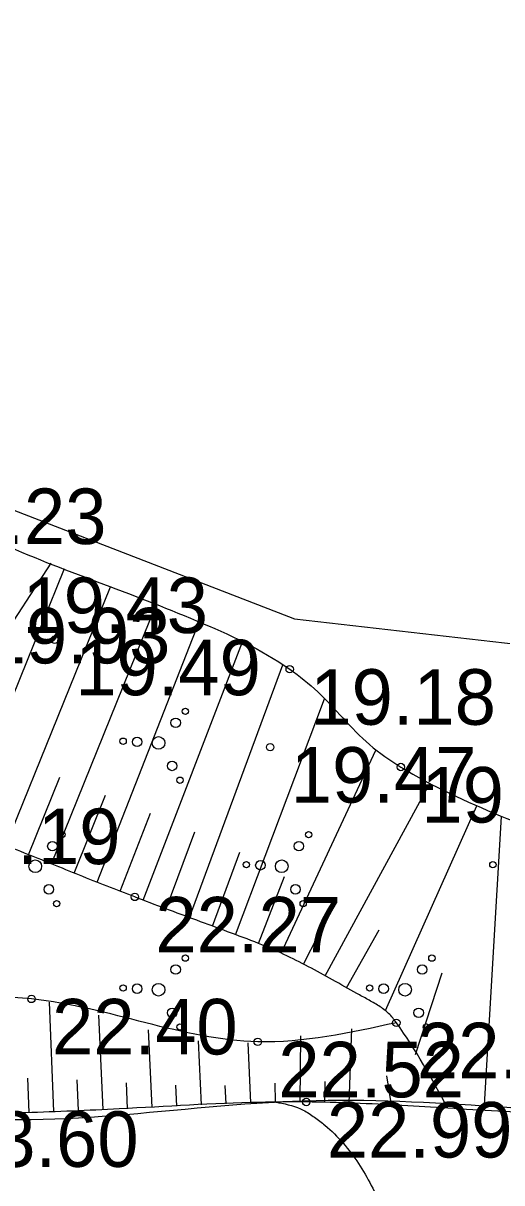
# Model space of a CAD drawing. Extents: x 521824 to 524158, y 294774 to 296228.
# Drawn here: x 522039.75 to 522049.46, y 296028.59 to 296052.08 of the extents above; entities that cross this region are included whole.
import ezdxf

# ---------------------------------------------------------------- set-up
doc = ezdxf.new("R2010")
doc.units = 0
for name, color, linetype in [('HIDG_PLIN_####_####_#', 7, 'Continuous'), ('RAMI_UZMR_####_####_#', 7, 'Continuous'), ('RELJ_AATZ_####_TKST_#', 7, 'Continuous'), ('RELJ_ELEM_####_####_#', 7, 'Continuous'), ('RELJ_HORZ_PAMT_####_#', 7, 'Continuous'), ('RELJ_NOGA_####_####_#', 7, 'Continuous'), ('RELJ_NOGL_####_####_#', 7, 'Continuous'), ('TERT_ELEM_####_####_#', 7, 'Continuous'), ('TERT_KONT_####_####_#', 7, 'Continuous')]:
    doc.layers.add(name, color=color, linetype=linetype)

msp = doc.modelspace()

# ---------------------------------------------------------------- linework, layer by layer
at = {"layer": 'HIDG_PLIN_####_####_#'}
for points in [[(522031.3024014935, 296050.69658941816), (522031.173, 296049.489), (522031.61527393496, 296047.3902310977), (522033.10356148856, 296045.5980747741), (522035.14856829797, 296044.0423810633), (522036.22693693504, 296043.3312858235), (522037.261, 296042.653), (522039.2199077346, 296041.5852114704), (522041.25685016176, 296040.7651794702), (522043.27086750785, 296039.9738077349), (522045.161, 296038.9920000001), (522045.72860179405, 296038.53251211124), (522046.2439666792, 296037.9979730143), (522046.78134822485, 296037.46519741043), (522047.41500000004, 296037.011), (522049.42746192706, 296036.01895480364)], [(522049.42746192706, 296036.01895480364), (522051.6761867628, 296035.315217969), (522053.955, 296035.24), (522056.633707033, 296035.67311548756), (522059.3118930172, 296036.18519992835), (522061.99338249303, 296036.7034344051), (522064.68200000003, 296037.1550000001), (522072.34578787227, 296038.30977781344), (522080.041, 296039.254), (522082.3829693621, 296039.4026833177), (522084.7289845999, 296039.4469387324), (522089.4278641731, 296039.3541311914), (522094.12706165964, 296039.23950805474), (522098.81599999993, 296039.367), (522103.92164475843, 296039.766797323), (522109.0253597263, 296040.2048024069), (522114.1296448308, 296040.6406562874), (522119.237, 296041.034), (522140.36100000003, 296042.353), (522146.41991366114, 296042.5193566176), (522152.48640362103, 296042.45253070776), (522158.5546917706, 296042.40393944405), (522161.5877045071, 296042.4650496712), (522164.619, 296042.625), (522170.455, 296046.167), (522171.0808804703, 296047.3956683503)]]:
    msp.add_spline(points, degree=3, dxfattribs=at)
at = {"layer": 'RAMI_UZMR_####_####_#'}
msp.add_lwpolyline([(522023.72900000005, 296021.723), (522015.46800000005, 296031.8340000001), (522031.173, 296049.489), (522037.43799330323, 296043.03493037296), (522045.25731776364, 296040.0155269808), (522064.8556709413, 296037.7736620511), (522081.00594674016, 296041.1695226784), (522170.455, 296046.16700000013), (522192.824, 296044.95), (522215.98600000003, 296046.637), (522238.336, 296053.36), (522285.71800000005, 296059.4810000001)], dxfattribs=at)
at = {"layer": 'RELJ_ELEM_####_####_#'}
for centre in [(522040.39300000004, 296039.5900000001), (522045.161, 296038.9920000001), (522044.766, 296037.414), (522047.41500000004, 296037.011), (522042.01900000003, 296034.379), (522039.922, 296032.313), (522047.324, 296031.83), (522044.51200000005, 296031.444), (522045.49600000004, 296030.22500000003)]:
    msp.add_circle(centre, 0.075, dxfattribs=at)
at = {"layer": 'RELJ_HORZ_PAMT_####_#'}
msp.add_spline([(522044.85511603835, 296030.2271374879), (522044.9393543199, 296030.211126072), (522045.43695187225, 296030.06102444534), (522045.66481904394, 296029.91473730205), (522045.87472485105, 296029.75335745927), (522046.24482291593, 296029.3900506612), (522046.81535865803, 296028.5343655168), (522047.21528780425, 296027.5696647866), (522047.37212762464, 296027.07008850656), (522047.51133906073, 296026.5716442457), (522047.60386530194, 296026.1102167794), (522047.6355158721, 296025.6393621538), (522047.50429819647, 296024.7127133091), (522047.3204629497, 296024.1396626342), (522047.0889714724, 296023.581931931), (522046.36231510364, 296022.6365536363), (522045.6357607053, 296022.0925054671), (522044.89907735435, 296021.6004896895), (522043.39228601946, 296020.6873365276), (522042.4956863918, 296020.17881377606), (522042.2431540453, 296019.9653614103), (522042.1228881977, 296019.8504953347), (522041.9945063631, 296019.7468091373), (522041.99450635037, 296019.7468091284)], degree=3, dxfattribs=at)
at = {"layer": 'RELJ_NOGA_####_####_#'}
for p, q in [((522037.30542762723, 296036.5203174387), (522040.3212533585, 296041.1374731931)), ((522038.47485720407, 296035.7985716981), (522040.59111517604, 296041.0299411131)), ((522039.40143422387, 296035.42246712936), (522041.52674599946, 296040.6583945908)), ((522040.328293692, 296035.04705917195), (522042.45124737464, 296040.2963518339)), ((522041.2566985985, 296034.6754984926), (522043.3247587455, 296039.95215513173)), ((522042.18891635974, 296034.3136080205), (522044.20323862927, 296039.54767968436)), ((522043.125155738, 296033.9622692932), (522045.02402357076, 296039.07879619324)), ((522044.06262160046, 296033.61419325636), (522045.8672821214, 296038.3898984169)), ((522044.98945663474, 296033.2394988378), (522046.9066250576, 296037.3536960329)), ((522039.8647662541, 296035.23452200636), (522040.50099092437, 296036.80767431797)), ((522045.8787823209, 296032.78272056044), (522048.0081429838, 296036.6926864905)), ((522040.7921559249, 296034.8604263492), (522041.426648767, 296036.4375983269)), ((522047.10256997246, 296032.0763575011), (522048.95580159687, 296036.22680422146)), ((522041.72244734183, 296034.4936260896), (522042.33625734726, 296036.0735669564)), ((522049.1031039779, 296030.05459219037), (522049.45672087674, 296036.0067186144)), ((522042.6564332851, 296034.13633610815), (522043.2361986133, 296035.6969619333)), ((522043.5939471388, 296033.7883882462), (522044.1498189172, 296035.2877651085)), ((522044.52982266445, 296033.436086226), (522045.058266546, 296034.7902614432)), ((522045.4383549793, 296033.0193946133), (522046.05219719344, 296034.205450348)), ((522046.3154707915, 296032.5392059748), (522046.9720996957, 296033.70985075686)), ((522047.7130780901, 296031.18511251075), (522048.2507699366, 296032.8426085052)), ((522040.37475794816, 296030.0298564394), (522040.2869711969, 296032.2464606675)), ((522041.37391497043, 296030.07089638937), (522041.2913209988, 296031.9829884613)), ((522047.1671589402, 296032.01960871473), (522047.167367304, 296032.0198245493)), ((522046.36999868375, 296030.20161998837), (522046.42400972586, 296031.706459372)), ((522042.3728908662, 296030.1161128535), (522042.2983916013, 296031.68788014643)), ((522043.37172993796, 296030.1642829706), (522043.3100130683, 296031.46478190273)), ((522045.3703368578, 296030.2272206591), (522045.3870088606, 296031.5641114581)), ((522047.4546972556, 296031.6131772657), (522047.4555536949, 296031.6136935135)), ((522044.3706641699, 296030.21041545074), (522044.3179143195, 296031.4229498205)), ((522047.71282115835, 296031.1849576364), (522047.7130780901, 296031.18511251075)), ((522047.2282299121, 296030.1654135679), (522047.1287915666, 296030.7566093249)), ((522047.97094506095, 296030.7567380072), (522047.97180150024, 296030.757254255)), ((522039.87514960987, 296030.01006987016), (522039.8475615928, 296030.7066637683)), ((522040.8743471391, 296030.05011841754), (522040.84884599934, 296030.67290693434)), ((522041.87343134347, 296030.0928754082), (522041.84961673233, 296030.61540043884)), ((522042.8723131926, 296030.14013964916), (522042.8516871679, 296030.5662206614)), ((522043.871167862, 296030.18798444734), (522043.8536994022, 296030.55608013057)), ((522044.8703569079, 296030.2273214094), (522044.863981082, 296030.60620715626)), ((522045.87021480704, 296030.2162675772), (522045.88177093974, 296030.64210577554)), ((522048.2290689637, 296030.32851837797), (522048.22932589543, 296030.32867325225)), ((522047.36901414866, 296030.15772371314), (522047.369068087, 296030.1587222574)), ((522047.8682002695, 296030.12921494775), (522047.8682179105, 296030.1295144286)), ((522048.36729814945, 296030.0992004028), (522048.3673595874, 296030.1001985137)), ((522048.60401264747, 296030.08471945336), (522048.60403096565, 296030.0850188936))]:
    msp.add_line(p, q, dxfattribs=at)
for points in [[(522175.44822488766, 296046.89139692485), (522175.23648820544, 296045.62185828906), (522174.43600000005, 296043.939), (522173.7601980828, 296043.1264046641), (522173.01994556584, 296042.4212369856), (522171.29213191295, 296041.3594377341), (522166.95800000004, 296040.08), (522163.37222974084, 296039.33976564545), (522159.7868774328, 296038.6560267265), (522152.587, 296037.951), (522149.6195980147, 296038.0779015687), (522146.6512227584, 296038.3770061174), (522143.681486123, 296038.70510760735), (522140.71, 296038.919), (522138.08806439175, 296039.05780376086), (522135.4583706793, 296039.1951056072), (522130.234, 296038.941), (522119.737, 296037.086), (522107.826, 296034.933), (522103.70260244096, 296034.2967720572), (522101.6333826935, 296034.0660227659), (522099.568, 296033.90400000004), (522097.1409175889, 296034.0390169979), (522094.7178065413, 296034.5339847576), (522092.294292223, 296035.08146013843), (522089.86600000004, 296035.374), (522087.5973311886, 296035.4146265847), (522085.3156540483, 296035.4019667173), (522080.75800000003, 296035.107), (522065.80600000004, 296032.8400000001), (522062.66896275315, 296032.1343702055), (522059.5595443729, 296031.2786179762), (522056.4381038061, 296030.4990567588), (522054.86048737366, 296030.20857073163), (522053.265, 296030.022), (522051.32281337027, 296029.96493036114), (522049.3805592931, 296030.0381085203), (522048.36729814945, 296030.0992004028)], [(522048.36729814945, 296030.0992004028), (522047.4382755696, 296030.1539824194), (522045.49600000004, 296030.22500000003), (522044.5481421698, 296030.2181364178), (522041.7045081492, 296030.0851765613), (522039.808740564, 296030.0074397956), (522037.913, 296030.036), (522035.7462344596, 296030.51300926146), (522033.73786981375, 296031.5575361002), (522031.87557026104, 296032.980044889), (522030.147, 296034.591), (522028.9365410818, 296036.00592391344), (522027.88978342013, 296037.5098279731), (522026.8366340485, 296038.9805680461), (522025.607, 296040.296), (522023.14334187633, 296042.44150423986)], [(522048.36756628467, 296030.0987555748), (522047.324, 296031.83), (522047.1669111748, 296032.0198479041), (522046.96704224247, 296032.1720355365), (522046.7450655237, 296032.3015943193), (522046.52165333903, 296032.42355567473), (522046.0315757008, 296032.6985041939), (522045.5402558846, 296032.9658452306), (522045.0415525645, 296033.2152227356), (522044.52932441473, 296033.4362806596), (522043.9024038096, 296033.6740325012), (522043.27383055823, 296033.90709244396), (522042.6454231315, 296034.1404263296), (522042.01900000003, 296034.379), (522040.89771892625, 296034.81795858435), (522039.7800103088, 296035.2687995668), (522038.66354653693, 296035.72224076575), (522037.54600000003, 296036.169), (522037.54599999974, 296036.169)]]:
    msp.add_spline(points, degree=3, dxfattribs=at)
at = {"layer": 'RELJ_NOGL_####_####_#'}
msp.add_spline([(522047.324, 296031.83), (522044.51200000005, 296031.444), (522039.922, 296032.313), (522034.22900000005, 296032.718), (522030.771, 296036.85500000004), (522026.286, 296043.819), (522025.909157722, 296044.1365076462)], degree=3, dxfattribs=at)
at = {"layer": 'TERT_ELEM_####_####_#'}
for centre, radius in [((522043.04400000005, 296038.13936), 0.06400000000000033), ((522042.84752, 296037.90767999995), 0.09600000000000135), ((522041.78160000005, 296037.53423999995), 0.06400000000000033), ((522042.06608, 296037.52079999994), 0.09600000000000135), ((522042.5, 296037.5), 0.12800000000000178), ((522042.77647999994, 296037.0331199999), 0.09600000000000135), ((522042.93392, 296036.74383999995), 0.06400000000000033), ((522040.54400000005, 296035.63936), 0.06400000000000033), ((522045.54400000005, 296035.63936), 0.06400000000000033), ((522040.34752, 296035.40767999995), 0.09600000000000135), ((522045.34752, 296035.40767999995), 0.09600000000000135), ((522040, 296035), 0.12800000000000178), ((522044.28160000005, 296035.03423999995), 0.06400000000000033), ((522044.56608, 296035.02079999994), 0.09600000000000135), ((522045, 296035), 0.12800000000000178), ((522049.28160000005, 296035.03423999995), 0.06400000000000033), ((522040.27647999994, 296034.5331199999), 0.09600000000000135), ((522045.27647999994, 296034.5331199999), 0.09600000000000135), ((522040.43392, 296034.24383999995), 0.06400000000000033), ((522045.43392, 296034.24383999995), 0.06400000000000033), ((522043.04400000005, 296033.13936), 0.06400000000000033), ((522048.04400000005, 296033.13936), 0.06400000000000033), ((522042.84752, 296032.90767999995), 0.09600000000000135), ((522047.84752, 296032.90767999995), 0.09600000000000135), ((522041.78160000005, 296032.53423999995), 0.06400000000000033), ((522042.06608, 296032.52079999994), 0.09600000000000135), ((522042.5, 296032.5), 0.12800000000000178), ((522046.78160000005, 296032.53423999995), 0.06400000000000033), ((522047.06608, 296032.52079999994), 0.09600000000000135), ((522047.5, 296032.5), 0.12800000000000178), ((522042.77647999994, 296032.0331199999), 0.09600000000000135), ((522047.77647999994, 296032.0331199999), 0.09600000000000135), ((522042.93392, 296031.74383999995), 0.06400000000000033), ((522047.93392, 296031.74383999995), 0.06400000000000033)]:
    msp.add_circle(centre, radius, dxfattribs=at)
at = {"layer": 'TERT_KONT_####_####_#'}
msp.add_spline([(522170.455, 296046.167), (522166.971340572, 296040.03181256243), (522160.901513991, 296038.7556647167), (522150.9608099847, 296037.90971206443), (522139.12419851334, 296038.9863790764), (522130.18268898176, 296038.9863790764), (522119.6415349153, 296036.95197828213), (522107.6012645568, 296034.8932966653), (522099.4638639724, 296033.9875679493), (522089.54878033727, 296035.37185410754), (522071.9219649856, 296033.7055837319), (522053.16785330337, 296029.9372491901), (522045.45612158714, 296030.2448683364), (522037.7700102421, 296029.98851904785), (522034.6955657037, 296030.9113764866), (522029.110324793, 296035.7563780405), (522025.3185098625, 296040.42193509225), (522023.12631726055, 296042.47261408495)], degree=3, dxfattribs=at)

# ---------------------------------------------------------------- texts
at = {"layer": 'RELJ_AATZ_####_TKST_#'}
for s, p in [(' 19.23', (522037.261, 296041.528)), (' 19.43', (522039.321, 296039.7260000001)), (' 19.93', (522038.558, 296039.11)), (' 19.49', (522040.39300000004, 296038.4650000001)), (' 19.18', (522045.161, 296037.8670000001)), (' 19.47', (522044.766, 296036.289)), (' 19.20', (522047.41500000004, 296035.886)), (' 22.19', (522037.54600000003, 296035.044)), (' 22.27', (522042.01900000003, 296033.254)), (' 22.40', (522039.922, 296031.188)), (' 22.29', (522047.324, 296030.705)), (' 22.52', (522044.51200000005, 296030.319)), (' 23.60', (522037.913, 296028.911)), (' 22.99', (522045.49600000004, 296029.10000000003))]:
    msp.add_text(s, height=1.125, dxfattribs=at).set_placement(p)

doc.saveas('drawing.dxf')
